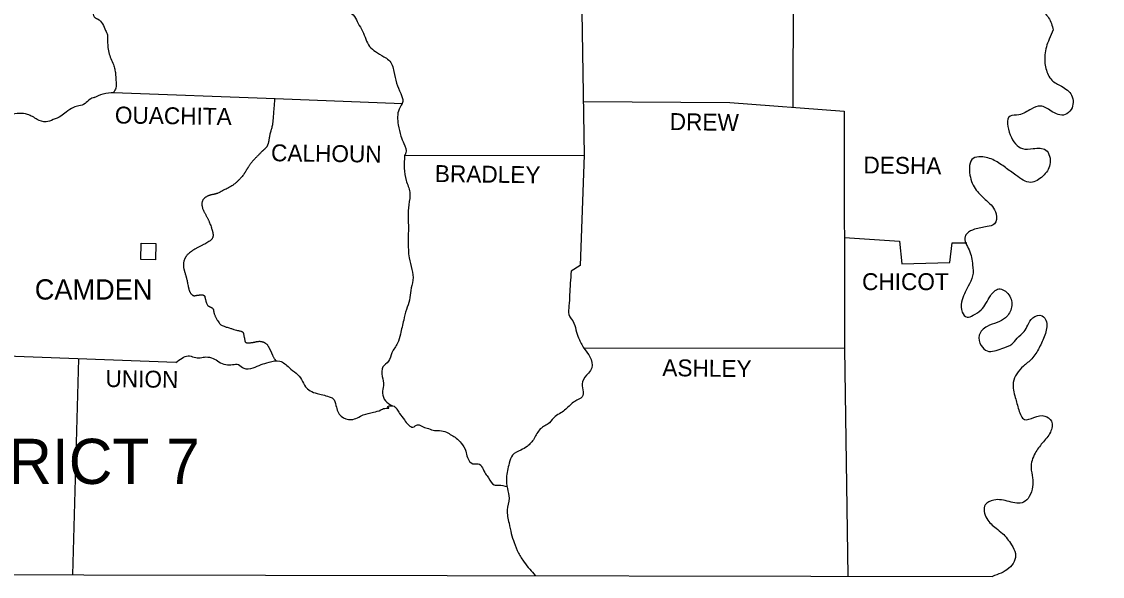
# Model space of a CAD drawing. Extents: x -0.68 to 1.92, y 0 to 0.95.
# Drawn here: x 1.1814 to 1.3056, y 0.5736 to 0.6375 of the extents above; entities that cross this region are included whole.
import ezdxf

# ---------------------------------------------------------------- set-up
doc = ezdxf.new("R2010")
doc.units = 0
doc.layers.add('Default', color=7, linetype='Continuous')

msp = doc.modelspace()

# ---------------------------------------------------------------- linework, layer by layer
at = {"layer": 'Default'}
for points in [[(1.24669, 0.6468), (1.24674, 0.64107), (1.24576, 0.64105), (1.24604, 0.62211)], [(1.27755, 0.64437), (1.27698, 0.64315), (1.27457, 0.64291), (1.27444, 0.64125), (1.27008, 0.64125), (1.27003, 0.62762)], [(1.19194, 0.62934), (1.21051, 0.62865), (1.22514, 0.62808)], [(1.24595, 0.62831), (1.26282, 0.62816), (1.27597, 0.62717)], [(1.27597, 0.62717), (1.276, 0.59986), (1.27636, 0.57365)], [(1.2254, 0.62206), (1.24604, 0.62211)], [(1.24604, 0.62211), (1.2456, 0.60941), (1.24456, 0.60876)], [(1.27598, 0.61264), (1.28232, 0.61223), (1.28258, 0.60961), (1.28811, 0.60977), (1.28837, 0.61203), (1.29007, 0.61203)], [(1.12566, 0.61083), (1.12576, 0.5739), (1.29301, 0.57362)], [(1.19908, 0.59823), (1.17962, 0.59896), (1.1795, 0.60378)], [(1.24603, 0.59991), (1.276, 0.59994)], [(1.1879, 0.59865), (1.18721, 0.5738)]]:
    msp.add_lwpolyline(points, dxfattribs=at)
msp.add_lwpolyline([(1.19506, 0.61011), (1.19511, 0.612), (1.19679, 0.61195), (1.19674, 0.61006)], close=True, dxfattribs=at)
for points in [[(1.33142, 0.69688), (1.33038, 0.69559), (1.32885, 0.69639), (1.32885, 0.69748), (1.32906, 0.69865), (1.32851, 0.69937), (1.32755, 0.69906), (1.32755, 0.69764), (1.32745, 0.69623), (1.32716, 0.69432), (1.32784, 0.69369), (1.32927, 0.69354), (1.33035, 0.69323), (1.33098, 0.69221), (1.33093, 0.69092), (1.33041, 0.6897), (1.32968, 0.68869), (1.32857, 0.68832), (1.32763, 0.6889), (1.32727, 0.69011), (1.32688, 0.69113), (1.32608, 0.6919), (1.32527, 0.69107), (1.32509, 0.68947), (1.32514, 0.68809), (1.32512, 0.6862), (1.32631, 0.68498), (1.32706, 0.68358), (1.3268, 0.68231), (1.32595, 0.68078), (1.32558, 0.67948), (1.32525, 0.67767), (1.32527, 0.67572), (1.32493, 0.6738), (1.32431, 0.6725), (1.32312, 0.67147), (1.32234, 0.67079), (1.32172, 0.67009), (1.32138, 0.66872), (1.32115, 0.66778), (1.32029, 0.66662), (1.31959, 0.66654), (1.31905, 0.66701), (1.31889, 0.66778), (1.31887, 0.66854), (1.31853, 0.66931), (1.31739, 0.66965), (1.31648, 0.66963), (1.31606, 0.66898), (1.31664, 0.66719), (1.31689, 0.66605), (1.31653, 0.66449), (1.31671, 0.66431), (1.31511, 0.66345), (1.31376, 0.6633), (1.31267, 0.66299), (1.3116, 0.66229), (1.31111, 0.6613), (1.31039, 0.6605), (1.30976, 0.65972), (1.30888, 0.65936), (1.30792, 0.65951), (1.30665, 0.65967), (1.3059, 0.65876), (1.30613, 0.65744), (1.30701, 0.65666), (1.30831, 0.6563), (1.30963, 0.65637), (1.3109, 0.6565), (1.31207, 0.65586), (1.31184, 0.65464), (1.3107, 0.65404), (1.30901, 0.65388), (1.30764, 0.65399), (1.306, 0.65362), (1.3052, 0.65256), (1.30567, 0.65101), (1.30743, 0.65033), (1.30823, 0.64883), (1.30828, 0.64743), (1.30769, 0.64553), (1.30686, 0.64468), (1.30528, 0.64434), (1.30406, 0.64408), (1.30385, 0.64198), (1.30333, 0.64097), (1.30237, 0.64063), (1.301, 0.64133), (1.30017, 0.64164), (1.29916, 0.64211), (1.29791, 0.64286), (1.29693, 0.64273), (1.29721, 0.64071), (1.29729, 0.64063), (1.2984, 0.6391), (1.29947, 0.63793), (1.29999, 0.63653)], [(1.18894, 0.64071), (1.18894, 0.63985), (1.18922, 0.63905), (1.18953, 0.63869), (1.18969, 0.63806), (1.1901, 0.6378), (1.19067, 0.63723), (1.19101, 0.63648), (1.19122, 0.63596), (1.19124, 0.63532), (1.19127, 0.63469), (1.19137, 0.63394), (1.19192, 0.63254), (1.19207, 0.632), (1.19215, 0.63153), (1.1922, 0.63075), (1.19218, 0.62984), (1.19194, 0.62934)], [(1.21707, 0.64037), (1.21811, 0.63967), (1.21897, 0.63874), (1.21962, 0.63809), (1.22006, 0.63729), (1.22057, 0.63638), (1.22138, 0.63464), (1.22205, 0.63404), (1.22301, 0.63345), (1.22358, 0.63306), (1.22418, 0.63174), (1.22447, 0.63041), (1.22496, 0.62922), (1.22519, 0.62831), (1.22478, 0.62741), (1.22467, 0.62559), (1.22498, 0.62432), (1.22532, 0.62344), (1.22555, 0.62237), (1.2254, 0.62206)], [(1.29999, 0.63653), (1.29952, 0.63547), (1.29903, 0.63366), (1.29916, 0.6321), (1.29983, 0.63075), (1.30095, 0.63005), (1.30211, 0.62901), (1.30206, 0.62738), (1.30136, 0.62678), (1.29975, 0.6272), (1.29853, 0.62777), (1.29747, 0.62743), (1.29604, 0.62676), (1.29503, 0.6266), (1.29506, 0.62445), (1.29646, 0.62287), (1.2977, 0.62287), (1.29913, 0.62271), (1.29962, 0.62105), (1.29879, 0.6197), (1.29742, 0.61898), (1.29571, 0.61981), (1.29449, 0.62069), (1.29322, 0.62152), (1.29169, 0.62193), (1.2908, 0.62175), (1.29042, 0.61983), (1.29114, 0.61809), (1.29234, 0.61688), (1.29342, 0.61535), (1.29324, 0.6142), (1.29241, 0.61389), (1.29096, 0.61358), (1.29008, 0.61309), (1.28987, 0.61275), (1.29031, 0.6112), (1.29073, 0.60948), (1.29073, 0.60821), (1.29023, 0.60702), (1.28946, 0.60521), (1.28953, 0.60404), (1.29008, 0.60347), (1.29078, 0.60368), (1.29169, 0.6043), (1.29226, 0.60505), (1.29278, 0.60593), (1.29374, 0.60671), (1.2949, 0.60604), (1.29521, 0.60463), (1.29451, 0.60339), (1.29355, 0.60285), (1.29239, 0.6024), (1.29148, 0.60139), (1.29171, 0.6002), (1.29241, 0.59958), (1.2941, 0.59986), (1.29524, 0.60036), (1.29586, 0.60103), (1.29664, 0.60181), (1.29706, 0.60256), (1.29765, 0.60339), (1.29871, 0.60362), (1.29921, 0.60292), (1.29903, 0.60139), (1.29838, 0.59994), (1.29752, 0.59867), (1.29656, 0.59781), (1.2954, 0.59595), (1.29563, 0.59421), (1.29604, 0.59278), (1.29669, 0.59169), (1.29778, 0.59193), (1.29903, 0.59208), (1.29978, 0.59149), (1.29967, 0.59022), (1.29874, 0.58897), (1.29791, 0.5878), (1.29744, 0.58612), (1.29763, 0.58498), (1.29763, 0.58394), (1.29724, 0.5828), (1.29659, 0.58215), (1.29493, 0.58223), (1.29316, 0.58241), (1.29218, 0.58186), (1.29236, 0.58028), (1.29342, 0.57917), (1.29415, 0.57857), (1.29519, 0.57727), (1.29565, 0.57624), (1.2955, 0.57533), (1.29488, 0.57455), (1.29301, 0.57362)], [(1.18969, 0.62875), (1.19075, 0.62919), (1.19194, 0.62934)], [(1.18969, 0.62875), (1.18922, 0.62855), (1.18865, 0.62805), (1.18795, 0.62779), (1.18733, 0.62761), (1.18647, 0.62707), (1.18587, 0.6266), (1.18499, 0.62621), (1.18416, 0.62595), (1.18315, 0.62624), (1.18261, 0.62655), (1.18204, 0.62681), (1.18009, 0.62681)], [(1.2254, 0.62206), (1.22558, 0.61921), (1.226, 0.61784), (1.22589, 0.61641), (1.22581, 0.61498), (1.22584, 0.61371), (1.22581, 0.61247), (1.22584, 0.6112), (1.22592, 0.61029), (1.22625, 0.60897), (1.22636, 0.60772), (1.2261, 0.60653), (1.22597, 0.60544), (1.22561, 0.60435), (1.2253, 0.60313), (1.22491, 0.60152), (1.22459, 0.60046), (1.22395, 0.59937), (1.22353, 0.59838), (1.22291, 0.59774), (1.22283, 0.59665), (1.22296, 0.59561), (1.22286, 0.5947), (1.22319, 0.59385), (1.224, 0.59325)], [(1.24456, 0.60876), (1.24446, 0.60736), (1.24438, 0.60604), (1.2443, 0.60476), (1.2443, 0.60378), (1.24488, 0.60277), (1.24516, 0.60173), (1.2455, 0.60087), (1.24612, 0.59976), (1.24672, 0.59888), (1.24692, 0.59763), (1.24654, 0.59701), (1.24586, 0.59602), (1.24581, 0.59429), (1.24498, 0.59377), (1.24394, 0.59286), (1.24337, 0.59245), (1.24272, 0.59203), (1.24205, 0.5913), (1.24101, 0.5906), (1.24029, 0.58949), (1.23948, 0.58858), (1.23878, 0.58817), (1.23782, 0.58757), (1.23743, 0.58666), (1.23712, 0.58495), (1.23722, 0.58373), (1.23741, 0.58262), (1.2372, 0.58127), (1.23741, 0.57974), (1.23767, 0.57855), (1.238, 0.57751), (1.2385, 0.57631), (1.23917, 0.57525), (1.24043, 0.57371)], [(1.19908, 0.59823), (1.19983, 0.59875), (1.2005, 0.59901), (1.2012, 0.59885), (1.2019, 0.5988), (1.20255, 0.59888), (1.20338, 0.59872), (1.20405, 0.59833), (1.20483, 0.598), (1.20561, 0.598), (1.20629, 0.598), (1.20691, 0.59758), (1.20797, 0.59763), (1.2089, 0.598), (1.20981, 0.59828), (1.21106, 0.59841), (1.21212, 0.59766), (1.21292, 0.59701), (1.21355, 0.59628), (1.21401, 0.59545), (1.21453, 0.59499), (1.21534, 0.59468), (1.21598, 0.59452), (1.21674, 0.59431), (1.21715, 0.59411), (1.21751, 0.59328), (1.21811, 0.59206), (1.21928, 0.59167), (1.22065, 0.59221), (1.22182, 0.59252), (1.22265, 0.59278), (1.22312, 0.59296), (1.22358, 0.59304), (1.22348, 0.59312), (1.224, 0.59325), (1.22452, 0.59289), (1.22483, 0.59239), (1.22537, 0.59164), (1.22587, 0.59102), (1.22636, 0.59081), (1.2269, 0.59107), (1.22755, 0.59084), (1.22815, 0.59063), (1.22885, 0.59042), (1.22942, 0.5904), (1.23022, 0.59022), (1.23079, 0.58988), (1.23134, 0.58954), (1.23191, 0.58897), (1.23245, 0.58804), (1.23263, 0.58731), (1.23326, 0.58658), (1.23388, 0.58658), (1.23471, 0.58542), (1.23505, 0.58495), (1.23572, 0.58415), (1.23621, 0.58412), (1.2372, 0.58397)]]:
    msp.add_spline(points, degree=3, dxfattribs=at)
msp.add_open_spline([(1.21045, 0.62865), (1.21038, 0.62772), (1.2103, 0.62678), (1.21023, 0.62585), (1.21021, 0.62561), (1.21015, 0.62538), (1.21009, 0.62514), (1.21005, 0.62503), (1.21002, 0.62491), (1.20998, 0.6248), (1.20995, 0.62468), (1.20992, 0.62457), (1.20989, 0.62445), (1.20984, 0.62423), (1.20982, 0.62401), (1.20978, 0.62379), (1.20976, 0.62368), (1.20974, 0.62357), (1.20971, 0.62346), (1.20969, 0.62341), (1.20967, 0.62336), (1.20965, 0.62331), (1.20964, 0.62328), (1.20963, 0.62325), (1.20962, 0.62323), (1.20961, 0.6232), (1.20959, 0.62318), (1.20958, 0.62315), (1.20954, 0.62308), (1.20949, 0.62301), (1.20943, 0.62294), (1.20937, 0.62288), (1.20931, 0.62282), (1.20925, 0.62277), (1.20919, 0.62271), (1.20912, 0.62266), (1.20906, 0.6226), (1.209, 0.62254), (1.20894, 0.62249), (1.20888, 0.62243), (1.20876, 0.6223), (1.20864, 0.62218), (1.20852, 0.62205), (1.20839, 0.62192), (1.20827, 0.6218), (1.20815, 0.62167), (1.20791, 0.62143), (1.20771, 0.62115), (1.2075, 0.62087), (1.20745, 0.62079), (1.20739, 0.62071), (1.20734, 0.62063), (1.20729, 0.62054), (1.20724, 0.62046), (1.20719, 0.62038), (1.20714, 0.62029), (1.20709, 0.62021), (1.20704, 0.62013), (1.20699, 0.62004), (1.20694, 0.61996), (1.20688, 0.61988), (1.20671, 0.61964), (1.2065, 0.61942), (1.20629, 0.61921), (1.20605, 0.61898), (1.20581, 0.61876), (1.20553, 0.61859), (1.20527, 0.61843), (1.205, 0.61829), (1.20473, 0.61815), (1.20445, 0.618), (1.20418, 0.61786), (1.2039, 0.61773), (1.20382, 0.6177), (1.20374, 0.61767), (1.20366, 0.61765), (1.20358, 0.61763), (1.2035, 0.61761), (1.20341, 0.61759), (1.20333, 0.61758), (1.20325, 0.61756), (1.20316, 0.61754), (1.20308, 0.61753), (1.203, 0.6175), (1.20291, 0.61747), (1.20278, 0.61743), (1.20266, 0.61737), (1.20254, 0.61729), (1.20248, 0.61726), (1.20243, 0.61722), (1.20238, 0.61717), (1.20236, 0.61714), (1.20233, 0.61712), (1.20231, 0.61709), (1.20228, 0.61706), (1.20226, 0.61704), (1.20224, 0.61701), (1.20218, 0.61692), (1.20215, 0.61683), (1.20212, 0.61674), (1.20209, 0.61664), (1.20208, 0.61654), (1.20208, 0.61645), (1.2021, 0.61626), (1.20214, 0.61607), (1.20221, 0.61589), (1.20227, 0.61576), (1.20233, 0.61563), (1.20239, 0.61551), (1.20246, 0.61538), (1.20253, 0.61526), (1.20259, 0.61513), (1.20266, 0.615), (1.20273, 0.61488), (1.20279, 0.61475), (1.20286, 0.61462), (1.20291, 0.61449), (1.20297, 0.61436), (1.20306, 0.61412), (1.20314, 0.61388), (1.20322, 0.61363), (1.20325, 0.61356), (1.20327, 0.61349), (1.20329, 0.61341), (1.20331, 0.61334), (1.20333, 0.61326), (1.20334, 0.61318), (1.20336, 0.61311), (1.20337, 0.61303), (1.20337, 0.61295), (1.20337, 0.61291), (1.20337, 0.61288), (1.20337, 0.61284), (1.20337, 0.6128), (1.20336, 0.61276), (1.20335, 0.61273), (1.20334, 0.61263), (1.20329, 0.61253), (1.20323, 0.61245), (1.20316, 0.61236), (1.20308, 0.61229), (1.20299, 0.61223), (1.20276, 0.61209), (1.20253, 0.61195), (1.20229, 0.61182), (1.202, 0.61166), (1.2017, 0.61151), (1.20141, 0.61135), (1.20115, 0.61121), (1.2009, 0.61104), (1.20066, 0.61086), (1.20053, 0.61076), (1.20042, 0.61065), (1.20032, 0.61052), (1.20027, 0.61046), (1.20023, 0.6104), (1.20019, 0.61033), (1.20015, 0.61026), (1.20012, 0.61018), (1.20009, 0.61011), (1.20002, 0.60993), (1.19998, 0.60975), (1.19997, 0.60957), (1.19996, 0.6094), (1.19997, 0.60922), (1.20001, 0.60904), (1.20003, 0.60894), (1.20006, 0.60884), (1.20009, 0.60874), (1.20012, 0.60864), (1.20015, 0.60854), (1.20018, 0.60843), (1.20021, 0.60833), (1.20024, 0.60823), (1.20027, 0.60813), (1.2003, 0.60803), (1.20032, 0.60793), (1.20035, 0.60782), (1.2004, 0.60758), (1.20045, 0.60732), (1.2005, 0.60707), (1.20053, 0.60697), (1.20055, 0.60686), (1.20058, 0.60675), (1.2006, 0.60664), (1.20064, 0.60654), (1.20068, 0.60643), (1.20072, 0.60633), (1.20077, 0.60624), (1.20084, 0.60616), (1.20088, 0.60611), (1.20091, 0.60608), (1.20096, 0.60604), (1.20098, 0.60603), (1.201, 0.60601), (1.20102, 0.606), (1.20105, 0.60598), (1.20107, 0.60597), (1.2011, 0.60596), (1.20113, 0.60594), (1.20117, 0.60593), (1.20121, 0.60593), (1.20125, 0.60593), (1.20128, 0.60594), (1.20132, 0.60595), (1.20136, 0.60595), (1.20139, 0.60596), (1.20143, 0.60597), (1.20147, 0.60598), (1.2015, 0.60598), (1.20154, 0.60598), (1.20157, 0.60599), (1.20161, 0.60599), (1.20164, 0.60599), (1.20168, 0.606), (1.20171, 0.606), (1.20175, 0.60601), (1.20182, 0.60602), (1.20189, 0.60603), (1.20195, 0.60604), (1.20202, 0.60605), (1.20209, 0.60605), (1.20216, 0.60603), (1.2022, 0.60603), (1.20223, 0.60602), (1.20227, 0.606), (1.20228, 0.60599), (1.2023, 0.60598), (1.20232, 0.60597), (1.20234, 0.60596), (1.20235, 0.60595), (1.20237, 0.60593), (1.2024, 0.6059), (1.20242, 0.60586), (1.20243, 0.60582), (1.20244, 0.60578), (1.20244, 0.60574), (1.20245, 0.6057), (1.20246, 0.60563), (1.20248, 0.60556), (1.2025, 0.60549), (1.20255, 0.60529), (1.20262, 0.60509), (1.20271, 0.60489), (1.20273, 0.60483), (1.20278, 0.60477), (1.20284, 0.60474), (1.20291, 0.60471), (1.20298, 0.60468), (1.20304, 0.60465), (1.20311, 0.60461), (1.20318, 0.60458), (1.20324, 0.60455), (1.2033, 0.60452), (1.20335, 0.60446), (1.20338, 0.6044), (1.2034, 0.60436), (1.20341, 0.60433), (1.20342, 0.60429), (1.20342, 0.60425), (1.20343, 0.60421), (1.20343, 0.60417), (1.20344, 0.60413), (1.20345, 0.60409), (1.20345, 0.60405), (1.20346, 0.60401), (1.20347, 0.60397), (1.20348, 0.60393), (1.20354, 0.60378), (1.2036, 0.60363), (1.20366, 0.60349), (1.20373, 0.60333), (1.20381, 0.60319), (1.2039, 0.60305), (1.20406, 0.6028), (1.20427, 0.60257), (1.20455, 0.60246), (1.20472, 0.60238), (1.20489, 0.60233), (1.20507, 0.60227), (1.20541, 0.60217), (1.20576, 0.60206), (1.2061, 0.60196), (1.20628, 0.60191), (1.20647, 0.60188), (1.20665, 0.60183), (1.20668, 0.60183), (1.2067, 0.60182), (1.20673, 0.6018), (1.2068, 0.60174), (1.20686, 0.60166), (1.20688, 0.60158), (1.2069, 0.60143), (1.20693, 0.60128), (1.20696, 0.60114), (1.20698, 0.601), (1.20701, 0.60086), (1.20704, 0.60072), (1.20705, 0.60066), (1.20708, 0.60062), (1.20713, 0.60057), (1.20717, 0.60054), (1.20722, 0.60052), (1.20727, 0.60051), (1.20739, 0.6005), (1.20751, 0.6005), (1.20763, 0.60052), (1.20775, 0.60053), (1.20788, 0.60054), (1.208, 0.60056), (1.20808, 0.60058), (1.20817, 0.6006), (1.20826, 0.60062), (1.20834, 0.60064), (1.20843, 0.60065), (1.20852, 0.60067), (1.20867, 0.60069), (1.20883, 0.60068), (1.20899, 0.60065), (1.20907, 0.60063), (1.20914, 0.60061), (1.20922, 0.60057), (1.20926, 0.60055), (1.2093, 0.60053), (1.20933, 0.60051), (1.20937, 0.60049), (1.20941, 0.60046), (1.20945, 0.60043), (1.20954, 0.60036), (1.20962, 0.60028), (1.20968, 0.60018), (1.20974, 0.60008), (1.20979, 0.59999), (1.20984, 0.59989), (1.20988, 0.59981), (1.20992, 0.59974), (1.20995, 0.59966), (1.20999, 0.59958), (1.21002, 0.5995), (1.21006, 0.59942), (1.21009, 0.59934), (1.21013, 0.59927), (1.21016, 0.59919), (1.2102, 0.59911), (1.21024, 0.59903), (1.21028, 0.59896), (1.21037, 0.59879), (1.21044, 0.59862), (1.21056, 0.59848)], degree=3, dxfattribs=at)

# ---------------------------------------------------------------- texts
for s, rotation, p in [('OUACHITA', 359.2027, (1.19207, 0.62577)), ('DREW', 359.1352, (1.25588, 0.62502)), ('CALHOUN', 359.2686, (1.21003, 0.62142)), ('DESHA', 359.2949, (1.27816, 0.62002)), ('BRADLEY', 359.2655, (1.22887, 0.61903)), ('ASHLEY', 359.2711, (1.25503, 0.59668)), ('UNION', 359.2015, (1.19099, 0.59543))]:
    msp.add_text(s, height=0.001945, rotation=rotation, dxfattribs=at).set_placement(p)
for s, height, p in [('CAMDEN', 0.002334, (1.18287, 0.60549)), ('CHICOT', 0.001945, (1.27801, 0.60658)), ('DISTRICT 7', 0.005203, (1.16397, 0.58426))]:
    msp.add_text(s, height=height, dxfattribs=at).set_placement(p)

doc.saveas('drawing.dxf')
